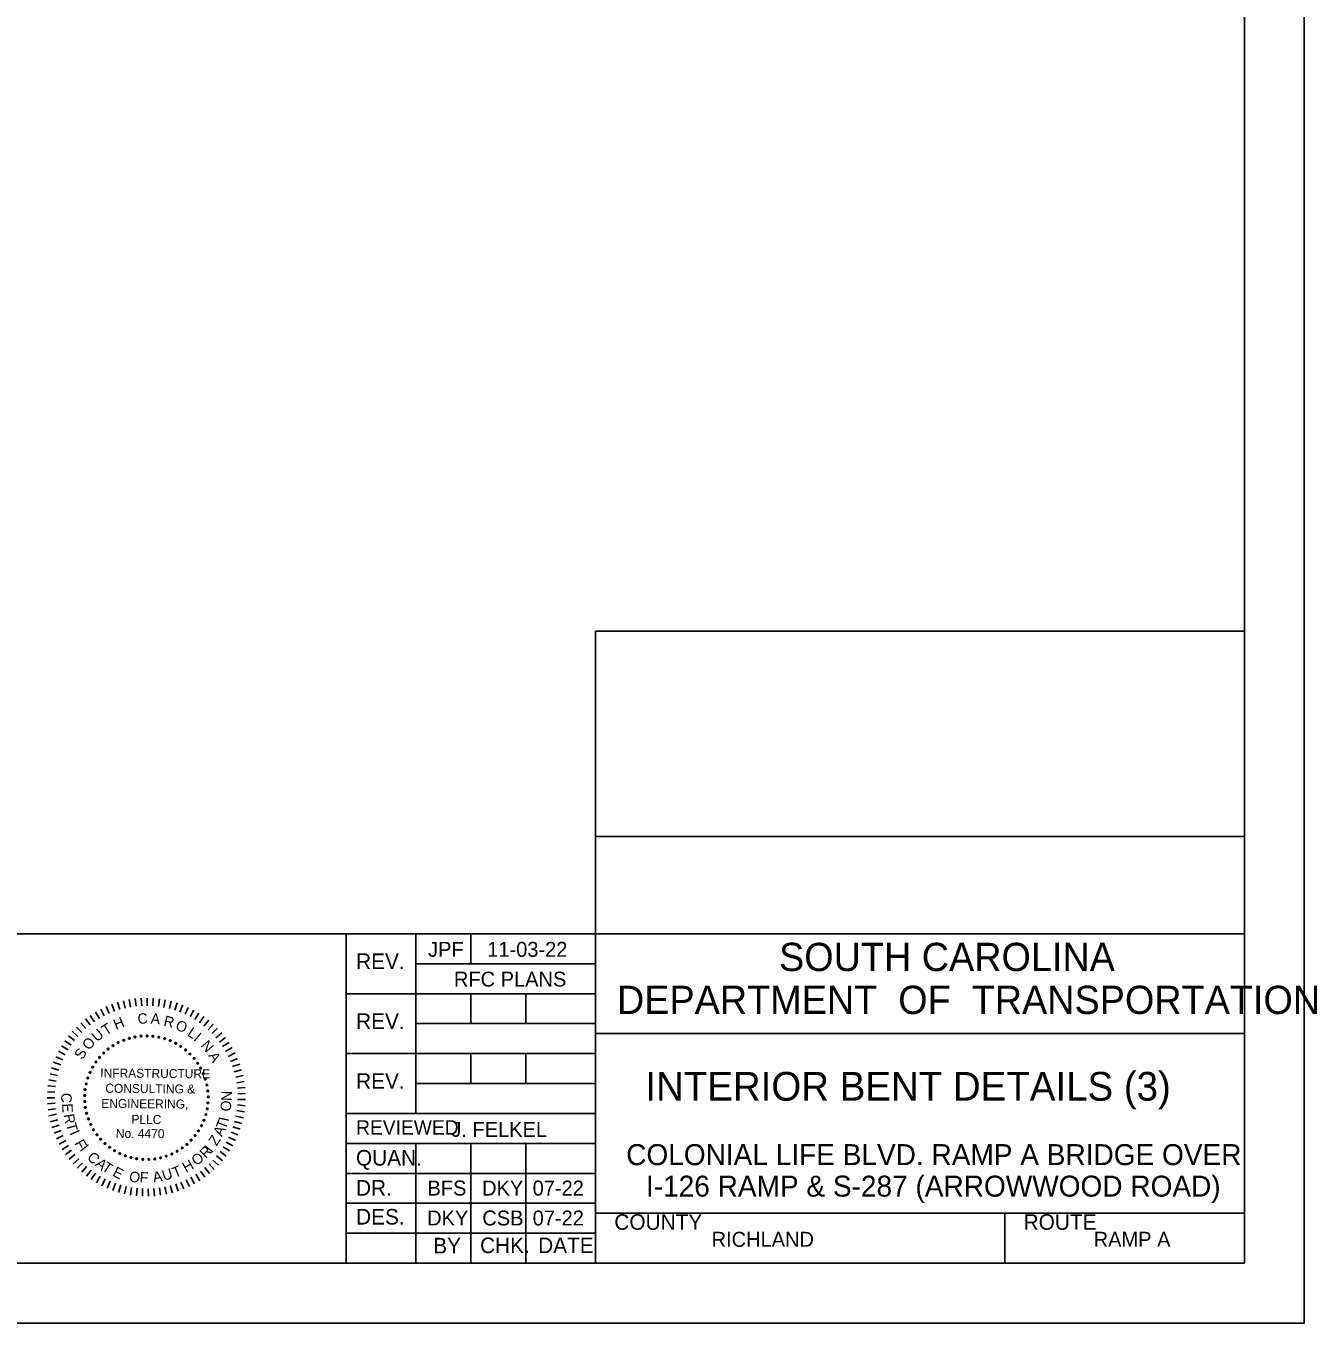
# Model space of a CAD drawing. Extents: x 1970675.2 to 1970711.3, y 796145.2 to 796167.2.
# Drawn here: x 1970700.56 to 1970711.34, y 796145.25 to 796156.08 of the extents above; entities that cross this region are included whole.
import ezdxf

# ---------------------------------------------------------------- set-up
doc = ezdxf.new("R2010")
doc.units = 0
for name, color, linetype in [('BR_BORDER LINES', 7, 'Continuous'), ('BR_TEXT', 7, 'Continuous'), ('Level 31', 7, 'Continuous')]:
    doc.layers.add(name, color=color, linetype=linetype)

msp = doc.modelspace()

# ---------------------------------------------------------------- linework, layer by layer
at = {"layer": 'BR_BORDER LINES'}
for p, q in [((1970710.736, 796145.746), (1970710.736, 796166.746)), ((1970705.319, 796145.746), (1970705.319, 796151.023)), ((1970705.319, 796151.023), (1970710.736, 796151.023)), ((1970705.319, 796149.308), (1970710.736, 796149.308)), ((1970697.87, 796148.496), (1970703.236, 796148.496)), ((1970703.236, 796145.746), (1970703.236, 796148.496)), ((1970703.236, 796148.496), (1970710.736, 796148.496)), ((1970703.819, 796148.496), (1970703.819, 796146.996)), ((1970704.277, 796148.246), (1970704.277, 796148.496)), ((1970703.819, 796148.246), (1970705.319, 796148.246)), ((1970703.236, 796147.996), (1970705.319, 796147.996)), ((1970704.277, 796147.746), (1970704.277, 796147.996)), ((1970704.736, 796147.746), (1970704.736, 796147.996)), ((1970703.819, 796147.746), (1970705.319, 796147.746)), ((1970705.319, 796147.663), (1970705.319, 796147.663)), ((1970705.319, 796147.663), (1970710.736, 796147.663)), ((1970703.236, 796147.496), (1970705.319, 796147.496)), ((1970704.277, 796147.246), (1970704.277, 796147.496)), ((1970704.736, 796147.246), (1970704.736, 796147.496)), ((1970703.819, 796147.246), (1970705.319, 796147.246)), ((1970703.236, 796146.996), (1970705.319, 796146.996)), ((1970703.236, 796146.746), (1970705.319, 796146.746)), ((1970703.819, 796146.746), (1970703.819, 796145.746)), ((1970704.277, 796146.746), (1970704.277, 796145.746)), ((1970704.736, 796146.746), (1970704.736, 796145.746)), ((1970703.236, 796146.496), (1970705.319, 796146.496)), ((1970703.236, 796146.246), (1970705.319, 796146.246)), ((1970705.319, 796146.163), (1970710.736, 796146.163)), ((1970705.417, 796146.163), (1970710.736, 796146.163)), ((1970708.736, 796145.746), (1970708.736, 796146.163)), ((1970703.236, 796145.996), (1970705.319, 796145.996)), ((1970677.07, 796145.746), (1970710.736, 796145.746))]:
    msp.add_line(p, q, dxfattribs=at)
at = {"layer": 'BR_TEXT'}
for p, q in [((1970701.233, 796147.889), (1970701.259, 796147.83)), ((1970701.28, 796147.908), (1970701.302, 796147.848)), ((1970701.328, 796147.924), (1970701.347, 796147.863)), ((1970701.377, 796147.937), (1970701.392, 796147.875)), ((1970701.426, 796147.947), (1970701.437, 796147.885)), ((1970701.476, 796147.955), (1970701.483, 796147.891)), ((1970701.526, 796147.959), (1970701.53, 796147.895)), ((1970701.577, 796147.96), (1970701.576, 796147.896)), ((1970701.627, 796147.958), (1970701.623, 796147.894)), ((1970701.678, 796147.953), (1970701.669, 796147.889)), ((1970701.727, 796147.944), (1970701.715, 796147.882)), ((1970701.777, 796147.933), (1970701.761, 796147.872)), ((1970701.825, 796147.919), (1970701.806, 796147.859)), ((1970701.873, 796147.902), (1970701.849, 796147.843)), ((1970701.919, 796147.882), (1970701.892, 796147.824)), ((1970701.061, 796147.785), (1970701.1, 796147.735)), ((1970701.101, 796147.815), (1970701.137, 796147.762)), ((1970701.144, 796147.842), (1970701.177, 796147.788)), ((1970701.188, 796147.867), (1970701.217, 796147.81)), ((1970701.964, 796147.859), (1970701.934, 796147.803)), ((1970702.008, 796147.834), (1970701.974, 796147.78)), ((1970702.05, 796147.806), (1970702.013, 796147.754)), ((1970702.09, 796147.775), (1970702.05, 796147.726)), ((1970700.95, 796147.682), (1970700.998, 796147.639)), ((1970700.985, 796147.718), (1970701.03, 796147.673)), ((1970701.022, 796147.753), (1970701.064, 796147.705)), ((1970702.128, 796147.742), (1970702.085, 796147.695)), ((1970702.164, 796147.707), (1970702.119, 796147.663)), ((1970702.198, 796147.67), (1970702.15, 796147.628)), ((1970700.861, 796147.56), (1970700.915, 796147.527)), ((1970700.888, 796147.602), (1970700.94, 796147.566)), ((1970700.918, 796147.643), (1970700.968, 796147.604)), ((1970702.23, 796147.631), (1970702.179, 796147.592)), ((1970702.259, 796147.589), (1970702.206, 796147.554)), ((1970700.814, 796147.47), (1970700.872, 796147.445)), ((1970700.836, 796147.516), (1970700.892, 796147.486)), ((1970702.286, 796147.546), (1970702.231, 796147.514)), ((1970702.31, 796147.502), (1970702.253, 796147.473)), ((1970702.331, 796147.456), (1970702.272, 796147.431)), ((1970700.778, 796147.376), (1970700.839, 796147.357)), ((1970700.795, 796147.424), (1970700.854, 796147.401)), ((1970702.349, 796147.409), (1970702.289, 796147.388)), ((1970702.364, 796147.361), (1970702.303, 796147.343)), ((1970700.754, 796147.278), (1970700.817, 796147.267)), ((1970700.765, 796147.327), (1970700.827, 796147.312)), ((1970702.377, 796147.312), (1970702.315, 796147.298)), ((1970702.386, 796147.263), (1970702.324, 796147.252)), ((1970700.741, 796147.127), (1970700.805, 796147.128)), ((1970700.743, 796147.178), (1970700.806, 796147.174)), ((1970700.747, 796147.228), (1970700.81, 796147.221)), ((1970702.393, 796147.212), (1970702.33, 796147.206)), ((1970702.396, 796147.162), (1970702.333, 796147.16)), ((1970700.743, 796147.077), (1970700.807, 796147.081)), ((1970700.748, 796147.027), (1970700.811, 796147.035)), ((1970702.388, 796147.011), (1970702.325, 796147.02)), ((1970702.394, 796147.061), (1970702.33, 796147.067)), ((1970702.397, 796147.112), (1970702.333, 796147.113)), ((1970700.756, 796146.977), (1970700.819, 796146.989)), ((1970700.767, 796146.927), (1970700.829, 796146.943)), ((1970702.367, 796146.912), (1970702.306, 796146.929)), ((1970702.379, 796146.961), (1970702.317, 796146.974)), ((1970700.781, 796146.879), (1970700.842, 796146.898)), ((1970700.798, 796146.831), (1970700.857, 796146.855)), ((1970700.818, 796146.785), (1970700.875, 796146.812)), ((1970702.314, 796146.771), (1970702.256, 796146.798)), ((1970702.334, 796146.817), (1970702.276, 796146.841)), ((1970702.352, 796146.864), (1970702.292, 796146.885)), ((1970700.84, 796146.74), (1970700.896, 796146.77)), ((1970700.866, 796146.696), (1970700.92, 796146.73)), ((1970700.893, 796146.654), (1970700.945, 796146.691)), ((1970702.264, 796146.683), (1970702.211, 796146.717)), ((1970702.29, 796146.726), (1970702.235, 796146.757)), ((1970700.924, 796146.614), (1970700.973, 796146.654)), ((1970700.957, 796146.575), (1970701.004, 796146.618)), ((1970700.992, 796146.539), (1970701.036, 796146.585)), ((1970702.171, 796146.564), (1970702.125, 796146.607)), ((1970702.204, 796146.602), (1970702.155, 796146.642)), ((1970702.236, 796146.641), (1970702.184, 796146.679)), ((1970701.029, 796146.505), (1970701.07, 796146.553)), ((1970701.068, 796146.473), (1970701.107, 796146.524)), ((1970701.109, 796146.444), (1970701.145, 796146.497)), ((1970702.016, 796146.435), (1970701.981, 796146.489)), ((1970702.057, 796146.464), (1970702.02, 796146.515)), ((1970702.097, 796146.495), (1970702.057, 796146.544)), ((1970702.135, 796146.528), (1970702.092, 796146.575)), ((1970701.152, 796146.417), (1970701.184, 796146.472)), ((1970701.196, 796146.393), (1970701.225, 796146.45)), ((1970701.242, 796146.372), (1970701.267, 796146.43)), ((1970701.289, 796146.353), (1970701.311, 796146.413)), ((1970701.337, 796146.337), (1970701.355, 796146.399)), ((1970701.386, 796146.325), (1970701.4, 796146.387)), ((1970701.436, 796146.315), (1970701.446, 796146.378)), ((1970701.486, 796146.309), (1970701.492, 796146.372)), ((1970701.536, 796146.305), (1970701.538, 796146.369)), ((1970701.586, 796146.305), (1970701.585, 796146.368)), ((1970701.637, 796146.307), (1970701.632, 796146.371)), ((1970701.687, 796146.313), (1970701.678, 796146.376)), ((1970701.737, 796146.322), (1970701.724, 796146.384)), ((1970701.786, 796146.333), (1970701.769, 796146.395)), ((1970701.834, 796146.348), (1970701.814, 796146.408)), ((1970701.881, 796146.366), (1970701.857, 796146.424)), ((1970701.928, 796146.386), (1970701.9, 796146.443)), ((1970701.972, 796146.409), (1970701.941, 796146.465))]:
    msp.add_line(p, q, dxfattribs=at)
for centre, start, end in [((1970701.291, 796147.562), 32.7576, 212.7576), ((1970701.291, 796147.562), 212.7576, 32.7576), ((1970701.334, 796147.587), 27.2191, 207.2191), ((1970701.334, 796147.587), 207.2191, 27.2191), ((1970701.38, 796147.607), 21.6807, 201.6807), ((1970701.38, 796147.607), 201.6807, 21.6807), ((1970701.427, 796147.624), 16.1422, 196.1422), ((1970701.427, 796147.624), 196.1422, 16.1422), ((1970701.475, 796147.635), 10.6038, 190.6038), ((1970701.475, 796147.635), 190.6038, 10.6038), ((1970701.525, 796147.642), 5.0653, 185.0653), ((1970701.525, 796147.642), 185.0653, 5.0653), ((1970701.575, 796147.644), 359.5268, 179.5268), ((1970701.575, 796147.644), 179.5268, 359.5268), ((1970701.624, 796147.641), 353.9884, 173.9884), ((1970701.624, 796147.641), 173.9884, 353.9884), ((1970701.673, 796147.633), 168.4499, 348.4499), ((1970701.673, 796147.633), 348.4499, 168.4499), ((1970701.722, 796147.621), 342.9114, 162.9114), ((1970701.722, 796147.621), 162.9114, 342.9114), ((1970701.769, 796147.604), 337.373, 157.373), ((1970701.769, 796147.604), 157.373, 337.373), ((1970701.814, 796147.582), 331.8345, 151.8345), ((1970701.814, 796147.582), 151.8345, 331.8345), ((1970701.856, 796147.556), 146.2961, 326.2961), ((1970701.856, 796147.556), 326.2961, 146.2961), ((1970701.178, 796147.464), 49.373, 229.373), ((1970701.178, 796147.464), 229.373, 49.373), ((1970701.213, 796147.501), 43.8345, 223.8345), ((1970701.213, 796147.501), 223.8345, 43.8345), ((1970701.25, 796147.533), 38.2961, 218.2961), ((1970701.25, 796147.533), 218.2961, 38.2961), ((1970701.896, 796147.527), 140.7576, 320.7576), ((1970701.896, 796147.527), 320.7576, 140.7576), ((1970701.933, 796147.493), 135.2191, 315.2191), ((1970701.933, 796147.493), 315.2191, 135.2191), ((1970701.967, 796147.456), 129.6807, 309.6807), ((1970701.967, 796147.456), 309.6807, 129.6807), ((1970701.099, 796147.339), 65.9884, 245.9884), ((1970701.099, 796147.339), 245.9884, 65.9884), ((1970701.121, 796147.383), 60.4499, 240.4499), ((1970701.121, 796147.383), 240.4499, 60.4499), ((1970701.148, 796147.425), 54.9114, 234.9114), ((1970701.148, 796147.425), 234.9114, 54.9114), ((1970701.997, 796147.416), 124.1422, 304.1422), ((1970701.997, 796147.416), 304.1422, 124.1422), ((1970702.022, 796147.374), 118.6038, 298.6038), ((1970702.022, 796147.374), 298.6038, 118.6038), ((1970701.067, 796147.244), 77.0653, 257.0653), ((1970701.067, 796147.244), 257.0653, 77.0653), ((1970701.08, 796147.292), 71.5268, 251.5268), ((1970701.08, 796147.292), 251.5268, 71.5268), ((1970702.044, 796147.329), 113.0653, 293.0653), ((1970702.044, 796147.329), 293.0653, 113.0653), ((1970702.061, 796147.282), 107.5268, 287.5268), ((1970702.061, 796147.282), 287.5268, 107.5268), ((1970702.074, 796147.234), 101.9884, 281.9884), ((1970702.074, 796147.234), 281.9884, 101.9884), ((1970701.054, 796147.146), 88.1422, 268.1422), ((1970701.058, 796147.195), 82.6038, 262.6038), ((1970701.054, 796147.146), 268.1422, 88.1422), ((1970701.058, 796147.195), 262.6038, 82.6038), ((1970702.082, 796147.185), 96.4499, 276.4499), ((1970702.085, 796147.135), 90.9114, 270.9114), ((1970702.082, 796147.185), 276.4499, 96.4499), ((1970702.085, 796147.135), 270.9114, 90.9114), ((1970701.055, 796147.096), 93.6807, 273.6807), ((1970701.06, 796147.046), 99.2191, 279.2191), ((1970701.055, 796147.096), 273.6807, 93.6807), ((1970701.06, 796147.046), 279.2191, 99.2191), ((1970702.077, 796147.036), 79.8345, 259.8345), ((1970702.077, 796147.036), 259.8345, 79.8345), ((1970702.083, 796147.085), 85.373, 265.373), ((1970702.083, 796147.085), 265.373, 85.373), ((1970701.07, 796146.998), 104.7576, 284.7576), ((1970701.07, 796146.998), 284.7576, 104.7576), ((1970701.085, 796146.95), 110.2961, 290.2961), ((1970701.085, 796146.95), 290.2961, 110.2961), ((1970701.105, 796146.904), 115.8345, 295.8345), ((1970701.105, 796146.904), 295.8345, 115.8345), ((1970702.05, 796146.94), 68.7576, 248.7576), ((1970702.05, 796146.94), 248.7576, 68.7576), ((1970702.065, 796146.987), 74.2961, 254.2961), ((1970702.065, 796146.987), 254.2961, 74.2961), ((1970701.128, 796146.86), 121.373, 301.373), ((1970701.128, 796146.86), 301.373, 121.373), ((1970701.156, 796146.819), 126.9114, 306.9114), ((1970701.156, 796146.819), 306.9114, 126.9114), ((1970701.976, 796146.811), 52.1422, 232.1422), ((1970701.976, 796146.811), 232.1422, 52.1422), ((1970702.004, 796146.851), 57.6807, 237.6807), ((1970702.004, 796146.851), 237.6807, 57.6807), ((1970702.029, 796146.895), 63.2191, 243.2191), ((1970702.029, 796146.895), 243.2191, 63.2191), ((1970701.188, 796146.781), 132.4499, 312.4499), ((1970701.188, 796146.781), 312.4499, 132.4499), ((1970701.223, 796146.745), 137.9884, 317.9884), ((1970701.223, 796146.745), 317.9884, 137.9884), ((1970701.262, 796146.714), 143.5268, 323.5268), ((1970701.262, 796146.714), 323.5268, 143.5268), ((1970701.303, 796146.686), 149.0653, 329.0653), ((1970701.303, 796146.686), 329.0653, 149.0653), ((1970701.868, 796146.708), 35.5268, 215.5268), ((1970701.868, 796146.708), 215.5268, 35.5268), ((1970701.907, 796146.738), 41.0653, 221.0653), ((1970701.907, 796146.738), 221.0653, 41.0653), ((1970701.943, 796146.773), 46.6038, 226.6038), ((1970701.943, 796146.773), 226.6038, 46.6038), ((1970701.347, 796146.662), 154.6038, 334.6038), ((1970701.347, 796146.662), 334.6038, 154.6038), ((1970701.393, 796146.643), 340.1422, 160.1422), ((1970701.393, 796146.643), 160.1422, 340.1422), ((1970701.441, 796146.628), 345.6807, 165.6807), ((1970701.441, 796146.628), 165.6807, 345.6807), ((1970701.489, 796146.618), 171.2191, 351.2191), ((1970701.489, 796146.618), 351.2191, 171.2191), ((1970701.539, 796146.613), 356.7576, 176.7576), ((1970701.539, 796146.613), 176.7576, 356.7576), ((1970701.589, 796146.613), 2.2961, 182.2961), ((1970701.589, 796146.613), 182.2961, 2.2961), ((1970701.639, 796146.617), 7.8345, 187.8345), ((1970701.639, 796146.617), 187.8345, 7.8345), ((1970701.688, 796146.626), 13.373, 193.373), ((1970701.688, 796146.626), 193.373, 13.373), ((1970701.735, 796146.64), 18.9114, 198.9114), ((1970701.735, 796146.64), 198.9114, 18.9114), ((1970701.782, 796146.658), 24.4499, 204.4499), ((1970701.782, 796146.658), 204.4499, 24.4499), ((1970701.826, 796146.681), 29.9884, 209.9884), ((1970701.826, 796146.681), 209.9884, 29.9884)]:
    msp.add_arc(centre, 0.00701, start, end, dxfattribs=at)
at = {"layer": 'Level 31'}
msp.add_line((1970708.028, 796147.223), (1970708.028, 796147.223), dxfattribs=at)
msp.add_lwpolyline([(1970675.236, 796167.246), (1970675.236, 796145.246), (1970711.236, 796145.246), (1970711.236, 796167.246)], dxfattribs=at)

# ---------------------------------------------------------------- texts
at = {"layer": 'BR_TEXT'}
for s, height, p in [('JPF', 0.125, (1970703.921, 796148.304)), ('11-03-22', 0.125, (1970704.415, 796148.304)), ('SOUTH CAROLINA', 0.23587, (1970706.851, 796148.185)), ('REV.', 0.13, (1970703.32, 796148.202)), ('RFC PLANS', 0.125, (1970704.137, 796148.055)), ('DEPARTMENT  OF  TRANSPORTATION', 0.23587, (1970705.498, 796147.827)), ('REV.', 0.13, (1970703.32, 796147.702)), ('INTERIOR BENT DETAILS (3)', 0.24, (1970705.735, 796147.103)), ('REV.', 0.13, (1970703.32, 796147.202)), ('REVIEWED', 0.12, (1970703.32, 796146.82)), ('J. FELKEL', 0.125, (1970704.115, 796146.801)), ('QUAN.', 0.13, (1970703.319, 796146.561)), ('COLONIAL LIFE BLVD. RAMP A BRIDGE OVER', 0.175, (1970705.575, 796146.565)), ('I-126 RAMP & S-287 (ARROWWOOD ROAD)', 0.175, (1970705.74, 796146.302)), ('DR.', 0.13, (1970703.319, 796146.31)), ('BFS', 0.125, (1970703.916, 796146.311)), ('DKY', 0.125, (1970704.372, 796146.311)), ('07-22', 0.125, (1970704.794, 796146.311)), ('DES.', 0.13, (1970703.32, 796146.069)), ('DKY', 0.125, (1970703.913, 796146.061)), ('CSB', 0.125, (1970704.374, 796146.061)), ('07-22', 0.125, (1970704.794, 796146.061)), ('COUNTY', 0.13, (1970705.476, 796146.025)), ('ROUTE', 0.13, (1970708.893, 796146.025)), ('BY', 0.13, (1970703.964, 796145.828)), ('CHK.', 0.13, (1970704.355, 796145.83)), ('DATE', 0.13, (1970704.84, 796145.83)), ('RICHLAND', 0.125, (1970706.288, 796145.883)), ('RAMP A', 0.125, (1970709.478, 796145.883))]:
    msp.add_text(s, height=height, dxfattribs=at).set_placement(p)
for s, height, rotation, p in [('H', 0.0872, 22.7882, (1970701.316, 796147.693)), ('C', 0.0872, 4.7281, (1970701.499, 796147.742)), ('A', 0.0872, 355.6981, (1970701.603, 796147.747)), ('R', 0.0872, 346.6681, (1970701.708, 796147.73)), ('O', 0.0872, 337.638, (1970701.805, 796147.7)), ('U', 0.0872, 40.8482, (1970701.158, 796147.589)), ('T', 0.0872, 31.8182, (1970701.231, 796147.645)), ('L', 0.0872, 327.108, (1970701.904, 796147.65)), ('I', 0.0872, 319.578, (1970701.957, 796147.612)), ('O', 0.0872, 49.8782, (1970701.091, 796147.518)), ('N', 0.0872, 310.548, (1970702.018, 796147.561)), ('S', 0.0872, 58.9083, (1970701.036, 796147.44)), ('A', 0.0872, 301.5179, (1970702.083, 796147.479)), ('INFRASTRUCTURE', 0.07477, 359.5268, (1970701.184, 796147.297)), ('CONSULTING &', 0.07477, 359.5268, (1970701.226, 796147.169)), ('C', 0.0872, 267.025, (1970700.861, 796147.17)), ('N', 0.0872, 89.2085, (1970702.282, 796147.1)), ('E', 0.0872, 273.025, (1970700.865, 796147.078)), ('ENGINEERING,', 0.07477, 359.5268, (1970701.192, 796147.043)), ('O', 0.0872, 83.2085, (1970702.271, 796147.009)), ('R', 0.0872, 279.025, (1970700.878, 796146.986)), ('T', 0.0872, 285.025, (1970700.895, 796146.907)), ('PLLC', 0.0748, 359.5268, (1970701.444, 796146.91)), ('T', 0.0872, 69.3954, (1970702.23, 796146.857)), ('I', 0.0872, 77.9093, (1970702.255, 796146.924)), ('I', 0.0872, 293.7713, (1970700.925, 796146.834)), ('No. 4470', 0.0748, 359.5268, (1970701.314, 796146.793)), ('Z', 0.0872, 57.3954, (1970702.155, 796146.72)), ('A', 0.0872, 63.3954, (1970702.199, 796146.797)), ('F', 0.0872, 299.7713, (1970700.966, 796146.748)), ('I', 0.0872, 308.5268, (1970701.008, 796146.694)), ('R', 0.0872, 44.5268, (1970702.065, 796146.615)), ('I', 0.0872, 52.3339, (1970702.114, 796146.662)), ('C', 0.0872, 314.5268, (1970701.068, 796146.624)), ('A', 0.0872, 320.5268, (1970701.137, 796146.565)), ('T', 0.0872, 326.5268, (1970701.191, 796146.527)), ('H', 0.0872, 28.5268, (1970701.9, 796146.499)), ('O', 0.0872, 38.5268, (1970701.988, 796146.555)), ('E', 0.0872, 332.5268, (1970701.28, 796146.479)), ('O', 0.0872, 350.5268, (1970701.42, 796146.43)), ('F', 0.0872, 356.5268, (1970701.511, 796146.421)), ('A', 0.0872, 10.5268, (1970701.631, 796146.42)), ('U', 0.0872, 16.5268, (1970701.715, 796146.433)), ('T', 0.0872, 22.5268, (1970701.807, 796146.457))]:
    msp.add_text(s, height=height, rotation=rotation, dxfattribs=at).set_placement(p)

doc.saveas('drawing.dxf')
